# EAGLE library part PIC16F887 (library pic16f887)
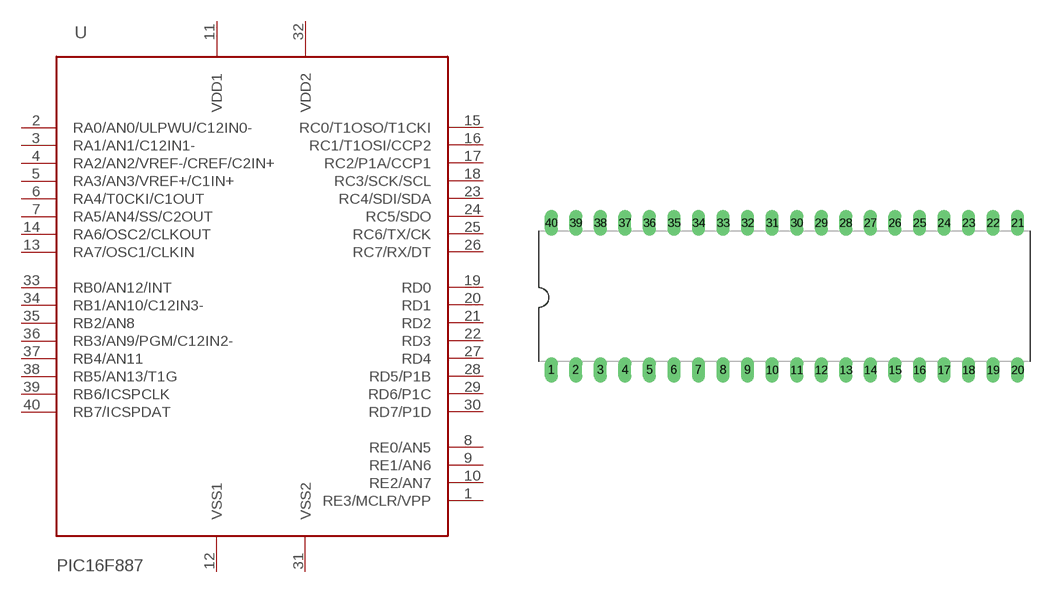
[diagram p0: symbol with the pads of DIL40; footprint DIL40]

Designator prefix -

## PIC16F887  [DIL40]
1  RE3/MCLR/VPP
2  RA0/AN0/ULPWU/C12IN0-
3  RA1/AN1/C12IN1-
4  RA2/AN2/VREF-/CREF/C2IN+
5  RA3/AN3/VREF+/C1IN+
6  RA4/T0CKI/C1OUT
7  RA5/AN4/SS/C2OUT
8  RE0/AN5
9  RE1/AN6
10  RE2/AN7
11  VDD1
12  VSS1
13  RA7/OSC1/CLKIN
14  RA6/OSC2/CLKOUT
15  RC0/T1OSO/T1CKI
16  RC1/T1OSI/CCP2
17  RC2/P1A/CCP1
18  RC3/SCK/SCL
19  RD0
20  RD1
21  RD2
22  RD3
23  RC4/SDI/SDA
24  RC5/SDO
25  RC6/TX/CK
26  RC7/RX/DT
27  RD4
28  RD5/P1B
29  RD6/P1C
30  RD7/P1D
31  VSS2
32  VDD2
33  RB0/AN12/INT
34  RB1/AN10/C12IN3-
35  RB2/AN8
36  RB3/AN9/PGM/C12IN2-
37  RB4/AN11
38  RB5/AN13/T1G
39  RB6/ICSPCLK
40  RB7/ICSPDAT

## Footprint DIL40 (pad centres in mm)
Dual In Line Package
drill 0.813 long: 1 -24.13,-7.62; 2 -21.59,-7.62; 3 -19.05,-7.62; 4 -16.51,-7.62; 5 -13.97,-7.62; 6 -11.43,-7.62; 7 -8.89,-7.62; 8 -6.35,-7.62; 9 -3.81,-7.62; 10 -1.27,-7.62; 11 1.27,-7.62; 12 3.81,-7.62; 13 6.35,-7.62; 14 8.89,-7.62; 15 11.43,-7.62; 16 13.97,-7.62; 17 16.51,-7.62; 18 19.05,-7.62; 19 21.59,-7.62; 20 24.13,-7.62; 21 24.13,7.62; 22 21.59,7.62; 23 19.05,7.62; 24 16.51,7.62; 25 13.97,7.62; 26 11.43,7.62; 27 8.89,7.62; 28 6.35,7.62; 29 3.81,7.62; 30 1.27,7.62; 31 -1.27,7.62; 32 -3.81,7.62; 33 -6.35,7.62; 34 -8.89,7.62; 35 -11.43,7.62; 36 -13.97,7.62; 37 -16.51,7.62; 38 -19.05,7.62; 39 -21.59,7.62; 40 -24.13,7.62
